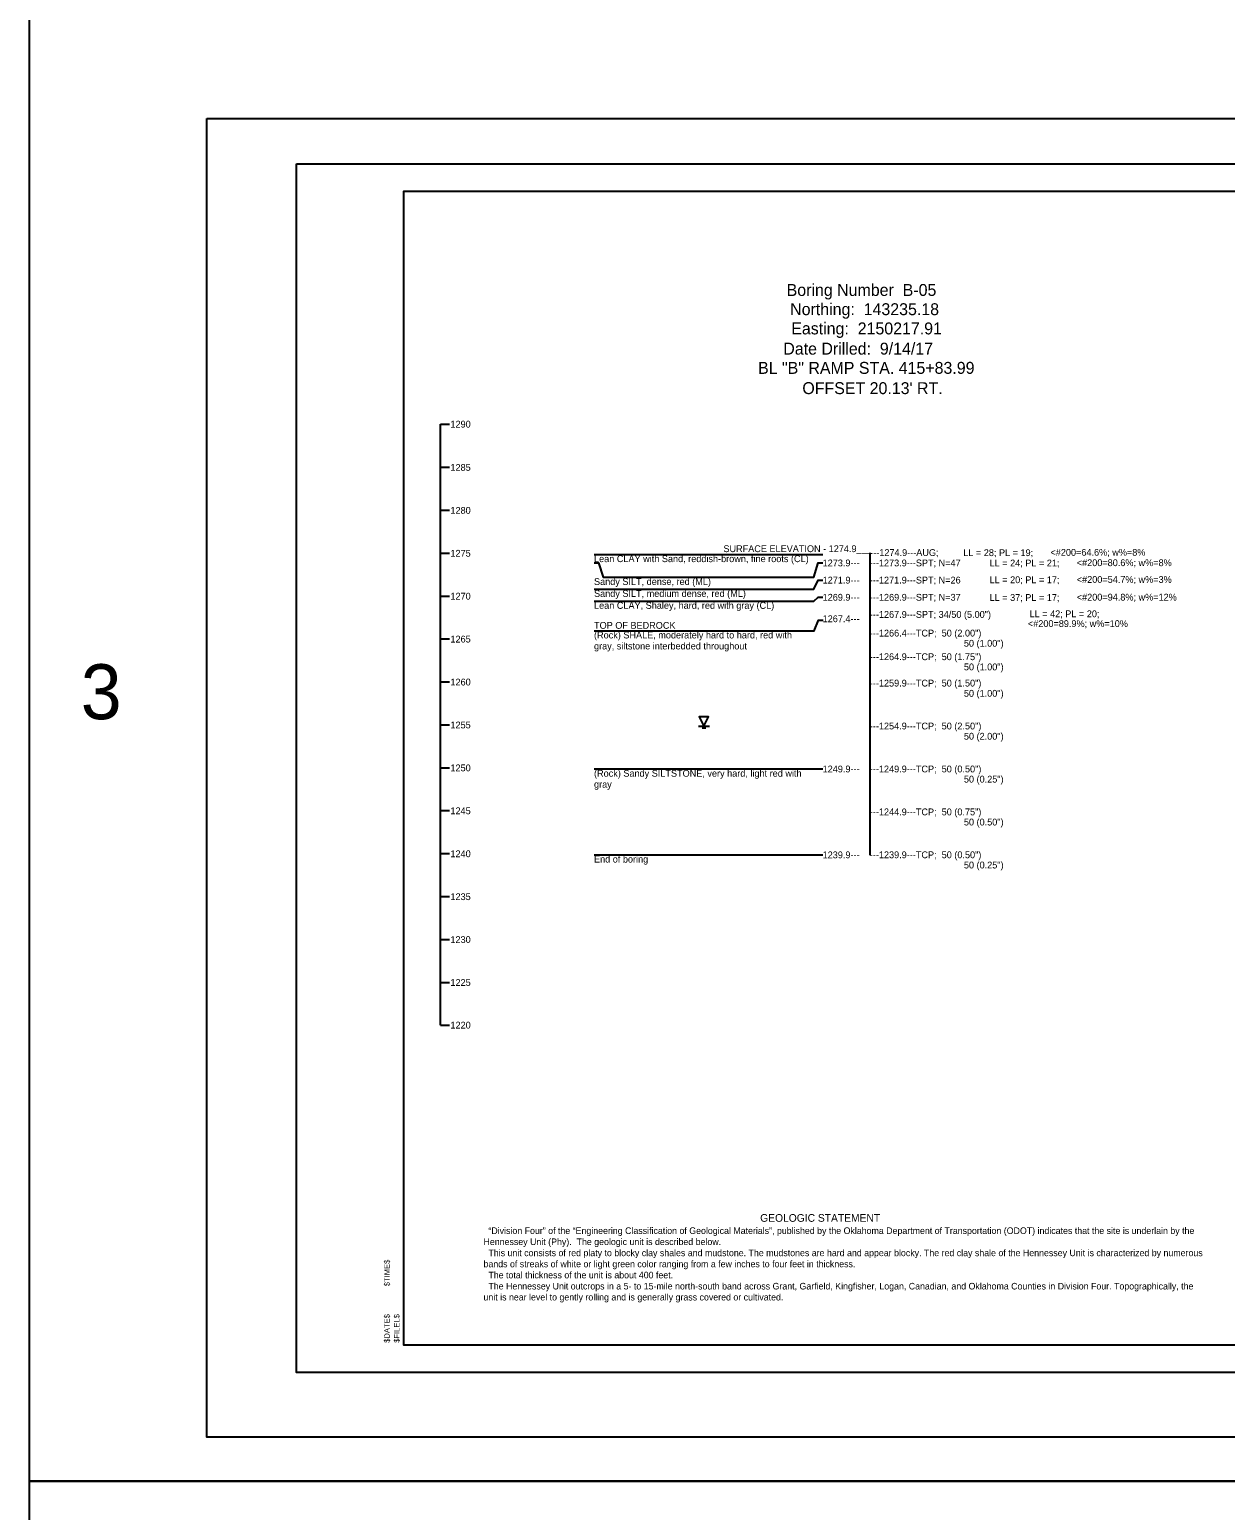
# Model space of a CAD drawing. Extents: x 2150162 to 2150245, y 143729 to 143865.
# Drawn here: x 2150161.57 to 2150183.34, y 143783.81 to 143810.76 of the extents above; entities that cross this region are included whole.
import ezdxf

# ---------------------------------------------------------------- set-up
doc = ezdxf.new("R2010")
doc.units = 0
for name, color, linetype in [('Default', 7, 'Continuous'), ('S', 7, 'Continuous'), ('SHT_Plot_Shape_Full', 7, 'Continuous'), ('SHT_Plot_Shape_Half', 7, 'Continuous'), ('SHT_Plot_Stamp', 7, 'Continuous'), ('SHT_Sheet_Border', 7, 'Continuous'), ('Text', 7, 'Continuous')]:
    doc.layers.add(name, color=color, linetype=linetype)

# ---------------------------------------------------------------- blocks, each defined once
blk = doc.blocks.new('Stamp_Plot_Stamp')
at = {"layer": 'SHT_Plot_Stamp'}
for s, p in [('$TIME$', (1.695, 1.572)), ('$DATE$', (1.695, 0.542)), ('$FILEL$', (1.873, 0.542))]:
    blk.add_text(s, height=0.1, rotation=90, dxfattribs=at).set_placement(p)
blk = doc.blocks.new('DGRFC_WTLEV1')
at = {"layer": 'Default'}
for points in [[(-0.0127, 0), (0.0127, 0)], [(0, 0), (0.0106, 0.0212), (-0.0106, 0.0212), (0, 0)], [(-0.0042, -0.0042), (0.0042, -0.0042)]]:
    blk.add_lwpolyline(points, dxfattribs=at)

msp = doc.modelspace()

# ---------------------------------------------------------------- linework, layer by layer
at = {"layer": 'Default'}
msp.add_line((2150169.048, 143792.641), (2150169.048, 143803.578), dxfattribs=at)
for points in [[(2150169.048, 143803.578), (2150169.214, 143803.578)], [(2150169.048, 143802.797), (2150169.214, 143802.797)], [(2150169.048, 143802.015), (2150169.214, 143802.015)], [(2150169.048, 143801.234), (2150169.214, 143801.234)], [(2150171.844, 143801.211), (2150176.011, 143801.211)], [(2150176.866, 143801.238), (2150176.866, 143795.736)], [(2150171.844, 143801.055), (2150171.927, 143801.055), (2150172.011, 143800.794), (2150175.844, 143800.794), (2150175.927, 143801.055), (2150176.011, 143801.055)], [(2150171.844, 143800.578), (2150175.844, 143800.578), (2150175.927, 143800.742), (2150176.011, 143800.742)], [(2150169.048, 143800.453), (2150169.214, 143800.453)], [(2150171.844, 143800.361), (2150175.844, 143800.361), (2150175.927, 143800.43), (2150176.011, 143800.43)], [(2150171.844, 143799.822), (2150175.854, 143799.822), (2150175.929, 143800.011), (2150176.016, 143800.011)], [(2150169.048, 143799.672), (2150169.214, 143799.672)], [(2150169.048, 143798.891), (2150169.214, 143798.891)], [(2150169.048, 143798.109), (2150169.214, 143798.109)], [(2150169.048, 143797.328), (2150169.214, 143797.328)], [(2150171.844, 143797.305), (2150176.011, 143797.305)], [(2150169.048, 143796.547), (2150169.214, 143796.547)], [(2150169.048, 143795.766), (2150169.214, 143795.766)], [(2150171.844, 143795.742), (2150176.011, 143795.742)], [(2150169.048, 143794.984), (2150169.214, 143794.984)], [(2150169.048, 143794.203), (2150169.214, 143794.203)], [(2150169.048, 143793.422), (2150169.214, 143793.422)], [(2150169.048, 143792.641), (2150169.214, 143792.641)]]:
    msp.add_lwpolyline(points, dxfattribs=at)
at = {"layer": 'S'}
for points in [[(2150203.404, 143784.341), (2150161.568, 143784.341), (2150161.568, 143865.061), (2150203.404, 143865.061)], [(2150161.568, 143784.341), (2150203.404, 143784.341), (2150203.404, 143729.315), (2150161.568, 143729.315)]]:
    msp.add_lwpolyline(points, close=True, dxfattribs=at)
at = {"layer": 'SHT_Plot_Shape_Full'}
msp.add_lwpolyline([(2150164.792, 143809.144), (2150200.792, 143809.144), (2150200.792, 143785.144), (2150164.792, 143785.144)], close=True, dxfattribs=at)
at = {"layer": 'SHT_Plot_Shape_Half'}
msp.add_lwpolyline([(2150166.429, 143808.319), (2150200.429, 143808.319), (2150200.429, 143786.319), (2150166.429, 143786.319)], close=True, dxfattribs=at)
at = {"layer": 'SHT_Sheet_Border'}
msp.add_lwpolyline([(2150199.879, 143786.819), (2150168.379, 143786.819), (2150168.379, 143807.819), (2150199.879, 143807.819)], close=True, dxfattribs=at)

# ---------------------------------------------------------------- block references
at = {"layer": 'Default', "xscale": 7.873999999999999, "yscale": 7.873999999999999}
msp.add_blockref('DGRFC_WTLEV1', (2150173.844, 143798.086), dxfattribs=at)
at = {"layer": 'SHT_Plot_Stamp'}
msp.add_blockref('Stamp_Plot_Stamp', (2150166.429, 143786.319), dxfattribs=at)

# ---------------------------------------------------------------- texts
at = {"layer": 'Default'}
for s, height, p in [('Boring Number  B-05', 0.217, (2150175.351, 143805.915)), ('Northing:  143235.18', 0.217, (2150175.415, 143805.565)), ('Easting:  2150217.91', 0.217, (2150175.435, 143805.215)), ('Date Drilled:  9/14/17', 0.217, (2150175.29, 143804.847)), ('BL "B" RAMP STA. 415+83.99', 0.217, (2150174.831, 143804.497)), ("OFFSET 20.13' RT.", 0.217, (2150175.637, 143804.128)), ('1290', 0.124, (2150169.23, 143803.519)), ('1285', 0.124, (2150169.23, 143802.732)), ('1280', 0.124, (2150169.23, 143801.95)), ('SURFACE ELEVATION - 1274.9___', 0.124, (2150174.2, 143801.252)), ('1275', 0.124, (2150169.23, 143801.169)), ('Lean CLAY with Sand, reddish-brown, fine roots (CL)', 0.124, (2150171.844, 143801.07)), ('1273.9---', 0.124, (2150176.006, 143800.993)), ('---1273.9---SPT; N=47', 0.124, (2150176.865, 143800.993)), ('---1274.9---AUG;', 0.124, (2150176.872, 143801.182)), ('LL = 28; PL = 19;', 0.124, (2150178.567, 143801.18)), ('LL = 24; PL = 21;', 0.124, (2150179.046, 143800.992)), ('<#200=64.6%; w%=8%', 0.124, (2150180.154, 143801.186)), ('<#200=80.6%; w%=8%', 0.124, (2150180.633, 143800.997)), ('Sandy SILT, dense, red (ML)', 0.124, (2150171.844, 143800.654)), ('Sandy SILT, medium dense, red (ML)', 0.124, (2150171.844, 143800.437)), ('1271.9---', 0.124, (2150176.006, 143800.68)), ('---1271.9---SPT; N=26', 0.124, (2150176.865, 143800.681)), ('LL = 20; PL = 17;', 0.124, (2150179.046, 143800.687)), ('<#200=54.7%; w%=3%', 0.124, (2150180.633, 143800.692)), ('1270', 0.124, (2150169.23, 143800.388)), ('Lean CLAY, Shaley, hard, red with gray (CL)', 0.124, (2150171.844, 143800.22)), ('1269.9---', 0.124, (2150176.006, 143800.368)), ('---1269.9---SPT; N=37', 0.124, (2150176.865, 143800.368)), ('LL = 37; PL = 17;', 0.124, (2150179.046, 143800.364)), ('<#200=94.8%; w%=12%', 0.124, (2150180.633, 143800.37)), ('1267.4---', 0.124, (2150176.006, 143799.977)), ('---1267.9---SPT; 34/50 (5.00")', 0.124, (2150176.865, 143800.056)), ('LL = 42; PL = 20;', 0.124, (2150179.774, 143800.067)), ('TOP OF BEDROCK', 0.124, (2150171.844, 143799.857)), ('(Rock) SHALE, moderately hard to hard, red with', 0.124, (2150171.844, 143799.681)), ('---1266.4---TCP;  50 (2.00")', 0.124, (2150176.865, 143799.716)), ('<#200=89.9%; w%=10%', 0.124, (2150179.743, 143799.889)), ('1265', 0.124, (2150169.23, 143799.607)), ('gray, siltstone interbedded throughout', 0.124, (2150171.844, 143799.481)), ('50 (1.00")', 0.124, (2150178.578, 143799.531)), ('---1264.9---TCP;  50 (1.75")', 0.124, (2150176.865, 143799.286)), ('50 (1.00")', 0.124, (2150178.578, 143799.101)), ('1260', 0.124, (2150169.23, 143798.825)), ('---1259.9---TCP;  50 (1.50")', 0.124, (2150176.865, 143798.806)), ('50 (1.00")', 0.124, (2150178.578, 143798.62)), ('1255', 0.124, (2150169.23, 143798.044)), ('---1254.9---TCP;  50 (2.50")', 0.124, (2150176.865, 143798.025)), ('50 (2.00")', 0.124, (2150178.578, 143797.839)), ('1250', 0.124, (2150169.23, 143797.263)), ('1249.9---', 0.124, (2150176.006, 143797.243)), ('---1249.9---TCP;  50 (0.50")', 0.124, (2150176.865, 143797.243)), ('gray', 0.124, (2150171.844, 143796.964)), ('(Rock) Sandy SILTSTONE, very hard, light red with', 0.124, (2150171.844, 143797.164)), ('50 (0.25")', 0.124, (2150178.578, 143797.058)), ('1245', 0.124, (2150169.23, 143796.482)), ('---1244.9---TCP;  50 (0.75")', 0.124, (2150176.865, 143796.462)), ('50 (0.50")', 0.124, (2150178.578, 143796.277)), ('1240', 0.124, (2150169.23, 143795.7)), ('End of boring', 0.124, (2150171.844, 143795.602)), ('1239.9---', 0.124, (2150176.006, 143795.68)), ('---1239.9---TCP;  50 (0.50")', 0.124, (2150176.865, 143795.681)), ('50 (0.25")', 0.124, (2150178.578, 143795.495)), ('1235', 0.124, (2150169.23, 143794.919)), ('1230', 0.124, (2150169.23, 143794.138)), ('1225', 0.124, (2150169.23, 143793.357)), ('1220', 0.124, (2150169.23, 143792.581))]:
    msp.add_text(s, height=height, dxfattribs=at).set_placement(p)
at = {"layer": 'S'}
msp.add_text('3', height=1, dxfattribs=at).set_placement((2150162.5, 143798.211))
at = {"layer": 'Text'}
for s, height, p in [('  “Division Four” of the “Engineering Classification of Geological Materials”, published by the Oklahoma Department of Transportation (ODOT) indicates that the site is underlain by the ', 0.12, (2150169.832, 143788.842)), ('GEOLOGIC STATEMENT', 0.14, (2150174.869, 143789.064)), ('Hennessey Unit (Phy).  The geologic unit is described below. ', 0.12, (2150169.832, 143788.64)), ('  This unit consists of red platy to blocky clay shales and mudstone. The mudstones are hard and appear blocky. The red clay shale of the Hennessey Unit is characterized by numerous ', 0.12, (2150169.832, 143788.438)), ('bands of streaks of white or light green color ranging from a few inches to four feet in thickness. ', 0.12, (2150169.832, 143788.236)), ('  The total thickness of the unit is about 400 feet.', 0.12, (2150169.832, 143788.034)), ('  The Hennessey Unit outcrops in a 5- to 15-mile north-south band across Grant, Garfield, Kingfisher, Logan, Canadian, and Oklahoma Counties in Division Four. Topographically, the ', 0.12, (2150169.832, 143787.832)), ('unit is near level to gently rolling and is generally grass covered or cultivated.', 0.12, (2150169.832, 143787.632))]:
    msp.add_text(s, height=height, dxfattribs=at).set_placement(p)

doc.saveas('drawing.dxf')
